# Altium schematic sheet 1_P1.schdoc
size 307 x 218 mm; Symbol: Drawing-Symbol_A4; Device: Drawing-Symbol_A4; Company: 嘉立创EDA; Version: V1.0; Page Size: A4; @Project Name: 罗兰霍尔半踏; @Page Count: 1; @Update Date: 2025-09-27; @Create Date: 2025-09-09; @Schematic Name: Schematic1; @Page No: 1; @Page Name: P1; @Create Time: 19:22:24; @Update Time: 16:03:37; Width: 1170; Height: 825; Region Start: 1; X Region Count: 6; Y Region Count: 4; Blade Width: 10; Title Block Position: 3; @Board Name: Board1
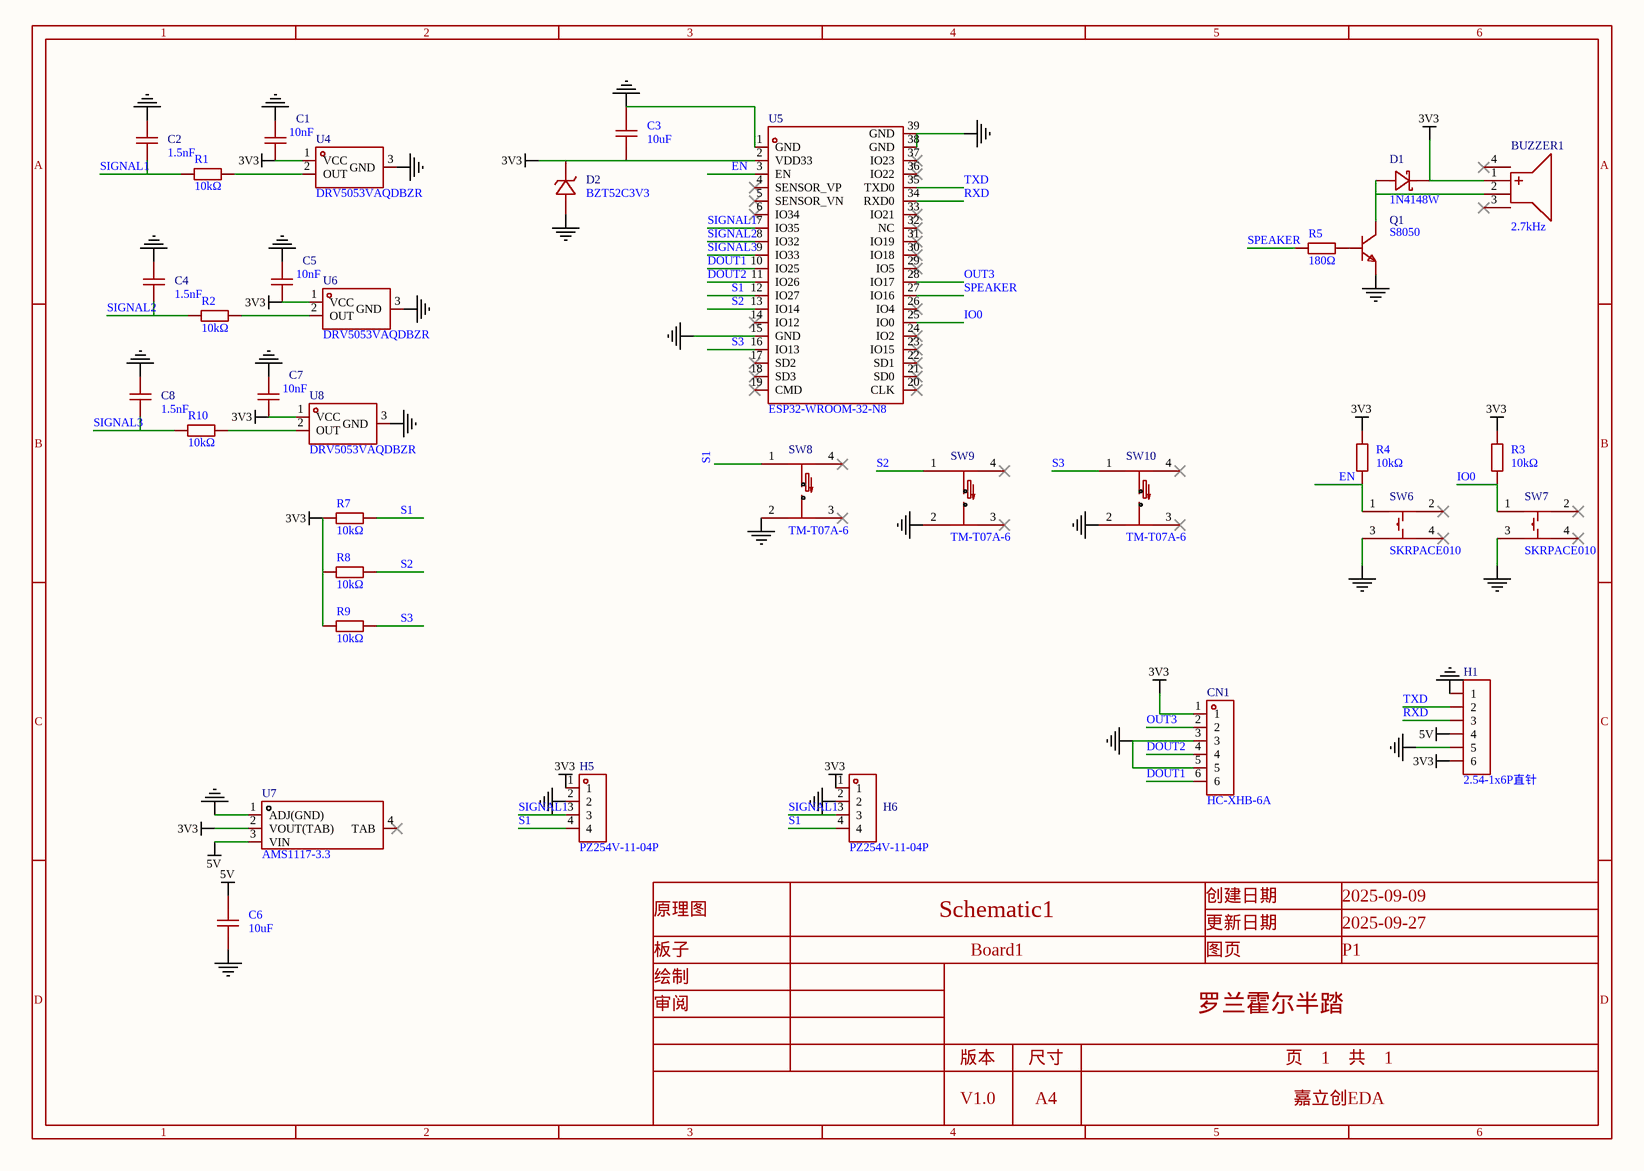
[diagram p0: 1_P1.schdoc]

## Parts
BUZZER1  2.7kHz  [BUZ-SMD_4P-L7.5-W7.5-P7.59-TL]
C1  10nF  [C0603]
C2  1.5nF  [C0603]
C3  10uF  [C0603]
C4  1.5nF  [C0603]
C5  10nF  [C0603]
C6  10uF  [C0603]
C7  10nF  [C0603]
C8  1.5nF  [C0603]
CN1  HC-XHB-6A  [CONN-TH_6P-P2.50_HCTL_HC-XHB-6A]
D1  1N4148W  [SOD-123_L2.7-W1.6-LS3.7-FD]
D2  BZT52C3V3  [SOD-123_L2.7-W1.6-LS3.7-RD]
H1  2.54-1x6P直针  [HDR-TH_6P-P2.54-V-M-1]
H5  PZ254V-11-04P  [HDR-TH_4P-P2.54-V-M]
H6  PZ254V-11-04P  [HDR-TH_4P-P2.54-V-M]
Q1  S8050  [SOT-23-3_L2.9-W1.3-P1.90-LS2.3-BR]
R1  10kΩ  [R0603]
R2  10kΩ  [R0603]
R3  10kΩ  [R0603]
R4  10kΩ  [R0603]
R5  180Ω  [R0603]
R7  10kΩ  [R0603]
R8  10kΩ  [R0603]
R9  10kΩ  [R0603]
R10  10kΩ  [R0603]
SW6  SKRPACE010  [KEY-SMD_4P-L4.2-W3.2-P2.20-LS4.6]
SW7  SKRPACE010  [KEY-SMD_4P-L4.2-W3.2-P2.20-LS4.6]
SW8  TM-T07A-6  [SW-SMD_TM-T07A-4]
SW9  TM-T07A-6  [SW-SMD_TM-T07A-4]
SW10  TM-T07A-6  [SW-SMD_TM-T07A-4]
U4  DRV5053VAQDBZR  [SOT-23-3_L2.9-W1.3-P1.90-LS2.4-BR]
U5  ESP32-WROOM-32-N8  [WIFIM-SMD_39P-L25.5-W18.0-P1.27]
U6  DRV5053VAQDBZR  [SOT-23-3_L2.9-W1.3-P1.90-LS2.4-BR]
U7  AMS1117-3.3  [SOT-223-4_L6.5-W3.5-P2.30-LS7.0-BR]
U8  DRV5053VAQDBZR  [SOT-23-3_L2.9-W1.3-P1.90-LS2.4-BR]

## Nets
3V3: BUZZER1.1(+) C1.1 C3.1 C5.1 C7.1 CN1.1 D1.2(K) D2.1(K) H1.6 H5.1 H6.1 R3.2 R4.2 R7.1 R8.1 R9.1 U4.1(VCC) U5.2(VDD33) U6.1(VCC) U7.2(VOUT(TAB)) U8.1(VCC)
5V: C6.2 H1.4 U7.3(VIN)
GND: C1.2 C2.2 C3.2 C4.2 C5.2 C6.1 C7.2 C8.2 CN1.3 CN1.5 D2.2(A) H1.1 H1.5 H5.2 H6.2 Q1.2(E) SW6.3 SW7.3 SW8.2 SW9.2 SW10.2 U4.3(GND) U5.1(GND) U5.15(GND) U5.38(GND) U5.39(GND) U6.3(GND) U7.1(ADJ(GND)) U8.3(GND)
DOUT1: CN1.6 U5.10(IO25)
DOUT2: CN1.4 U5.11(IO26)
EN: R4.1 SW6.1 U5.3(EN)
IO0: R3.1 SW7.1 U5.25(IO0)
OUT3: CN1.2 U5.28(IO17)
RXD: H1.3 U5.34(RXD0)
S1: H5.4 H6.4 R7.2 SW8.1 U5.12(IO27)
S2: R8.2 SW9.1 U5.13(IO14)
S3: R9.2 SW10.1 U5.16(IO13)
SIGNAL1: C2.1 H5.3 H6.3 R1.1 U5.7(IO35)
SIGNAL2: C4.1 R2.1 U5.8(IO32)
SIGNAL3: C8.1 R10.1 U5.9(IO33)
SPEAKER: R5.1 U5.27(IO16)
TXD: H1.2 U5.35(TXD0)
NetBUZZER1_2: BUZZER1.2(-) D1.1(A) Q1.3(C)
NetQ1_1: Q1.1(B) R5.2
NetR1_2: R1.2 U4.2(OUT)
NetR2_2: R2.2 U6.2(OUT)
NetR10_2: R10.2 U8.2(OUT)

Not connected (* = marked no-connect by the designer): BUZZER1 3* 4*; SW6 2* 4*; SW7 2* 4*; SW8 3* 4*; SW9 3* 4*; SW10 3* 4*; U5 4(SENSOR_VP)* 5(SENSOR_VN)* 6(IO34)* 14(IO12)* 17(SD2)* 18(SD3)* 19(CMD)* 20(CLK)* 21(SD0)* 22(SD1)* 23(IO15)* 24(IO2)* 26(IO4)* 29(IO5)* 30(IO18)* 31(IO19)* 32(NC)* 33(IO21)* 36(IO22)* 37(IO23)*; U7 4(TAB)*

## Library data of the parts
BUZZER1 = MLT-7525: Manufacturer: 华能; Add into BOM: yes; Driver Circuitry: 无源(外部驱动); Voltage - Supply: 2.5V~4.5V; Sound Pressure Level(SPL): 80dB
C1 C5 C7 = CC0603KRX7R9BB103: Manufacturer: YAGEO(国巨); Symbol: CL05B103KB5NNNC; Add into BOM: yes; Tolerance: ±10%; Voltage Rating: 50V; Temperature Coefficient: X7R
C2 C4 C8 = CC0603JRNPO9BN152: Manufacturer: YAGEO(国巨); Add into BOM: yes; Tolerance: ±5%; Voltage Rating: 50V; Temperature Coefficient: NP0
C3 C6 = CL10A106MA8NRNC: Manufacturer: SAMSUNG(三星); Symbol: CapAcitance; Add into BOM: yes; Tolerance: ±20%; Voltage Rating: 25V; Temperature Coefficient: X5R
CN1 = HC-XHB-6A: Manufacturer: HCTL(华灿天禄); Add into BOM: yes; Pins Structure: 1x6P; Pitch: 2.5mm; Reference Series: XHB; Number of PINs Per Row: 6; Current Rating: 3A; Voltage Rating: 250V; Plastic Material: PA66; Flame Retardant Rating: UL94V-0; Z-Height of the Board: 7.1mm; X-Length of Bottom Edge on Board (Spacing Line): 17.5mm; Y-Width of Bottom Edge on Board: 6.35mm
D1 = 1N4148W_C7420318: Manufacturer: R+O(宏嘉诚); Add into BOM: yes; Diode Configuration: 独立式; Voltage - Forward(Vf@If): 1.25V@150mA; Voltage - DC Reverse(Vr): 100V; Current - Rectified: 150mA; Pd - Power Dissipation: 400mW; Reverse Leakage Current (Ir): 1uA@75V; Reverse Recovery Time (trr): 4ns; Operating Junction Temperature Range: -55℃~+150℃; Non-Repetitive Peak Forward Surge Current: 2A
D2 = BZT52C3V3_C19077396: Manufacturer: R+O(宏嘉诚); Add into BOM: yes; Diode Configuration: 独立式; Zener Voltage(Nom): 3.3V; Reverse Leakage Current (Ir): 5uA; Zener Voltage(Range): 3.14V~3.47V; Pd - Power Dissipation: 350mW; Impedance(Zzt): 95Ω; Impedance(Zzk): 600Ω; Operating Junction Temperature Range: -55℃~+150℃
H1 = 2.54-1x6P直针: Manufacturer: BOOMELE(博穆精密); Symbol: Header-Male-2.54_1x6; Add into BOM: yes; Pin Structure: 1x6P; Pitch: 2.54mm; Circluar Pins/Square Pins: 方针; Current Rating: 3A
H5 H6 = PZ254V-11-04P: Manufacturer: XFCN(兴飞); Symbol: PZ254V-11-04P_C2691448; Add into BOM: yes; Pin Structure: 1x4P; Pitch: 2.54mm; Circluar Pins/Square Pins: 方针; Current Rating: 3A; Voltage Rating (Max): 250V
Q1 = S8050_C20069125: Manufacturer: R+O(宏嘉诚); Add into BOM: yes; type: NPN; Current - Collector(Ic): 500mA; Collector - Emitter Voltage VCEO: 25V; Pd - Power Dissipation: 300mW; DC Current Gain: 120@50mA,1.0V; Transition frequency(fT): 100MHz; Current - Collector Cutoff: 100nA; Vce Saturation(VCE(sat)): 600mV@500mA,50mA; Emitter-Base Voltage(Vebo): 5V
R1-R4 R7-R10 = 0603WAF1002T5E: Manufacturer: UNI-ROYAL(厚声); Symbol: 电阻; Add into BOM: yes; Tolerance: ±1%; Power(Watts): 100mW; Voltage-Supply(Max): 75V; Temperature Coefficient: ±100ppm/℃
R5 = 0603WAF1800T5E: Manufacturer: UNI-ROYAL(厚声); Symbol: 电阻; Add into BOM: yes; Tolerance: ±1%; Power(Watts): 100mW; Overload Voltage (Max): 75V; Temperature Coefficient: ±100ppm/℃
SW6 SW7 = SKRPACE010: Manufacturer: ALPSALPINE(阿尔卑斯阿尔派); Add into BOM: yes; Circuit: 单刀单掷; Actuator Style: 椭圆形按钮; Switch Height: 2.5mm; Contact Current: 50mA; Voltage Rating: 16V
SW8-SW10 = TM-T07A-6: Manufacturer: XKB Connection(中国星坤); Add into BOM: yes; Circuit: 双刀单掷-常开; Switch Height: 4.9mm; Current Rating (DC): 100mA; Voltage Rating (DC): 30V; Life: 10万次
U4 U6 U8 = DRV5053VAQDBZR: Manufacturer: TI(德州仪器); Add into BOM: yes; Voltage - Supply: 2.5V~38V
U5 = ESP32-WROOM-32-N8: Manufacturer: ESPRESSIF(乐鑫); Symbol: ESP32-WROOM-32(8MB); Add into BOM: yes
U7 = AMS1117-3.3_C347222: Manufacturer: UMW(友台半导体); Add into BOM: yes; Output Type: 固定; Voltage - Supply: 12V; Output Voltage: 3.3V; Output Current: 1A; Power Supply Rejection Ratio (PSRR): 60dB@(120Hz); Voltage Dropout: 1.3V@(1A); Output Configuration: 正极; Number of Outputs: 1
